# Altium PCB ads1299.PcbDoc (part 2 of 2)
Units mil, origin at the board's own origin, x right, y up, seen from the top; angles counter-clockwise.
Board outline 3937.01 x 3937.01 mil, 4 copper layers (Top Layer, internal_Layer 1, Internal_Layer 2, Bottom Layer), stack 23.756 mil thick; 175 components, 124 nets, 575 pads, 101 vias.
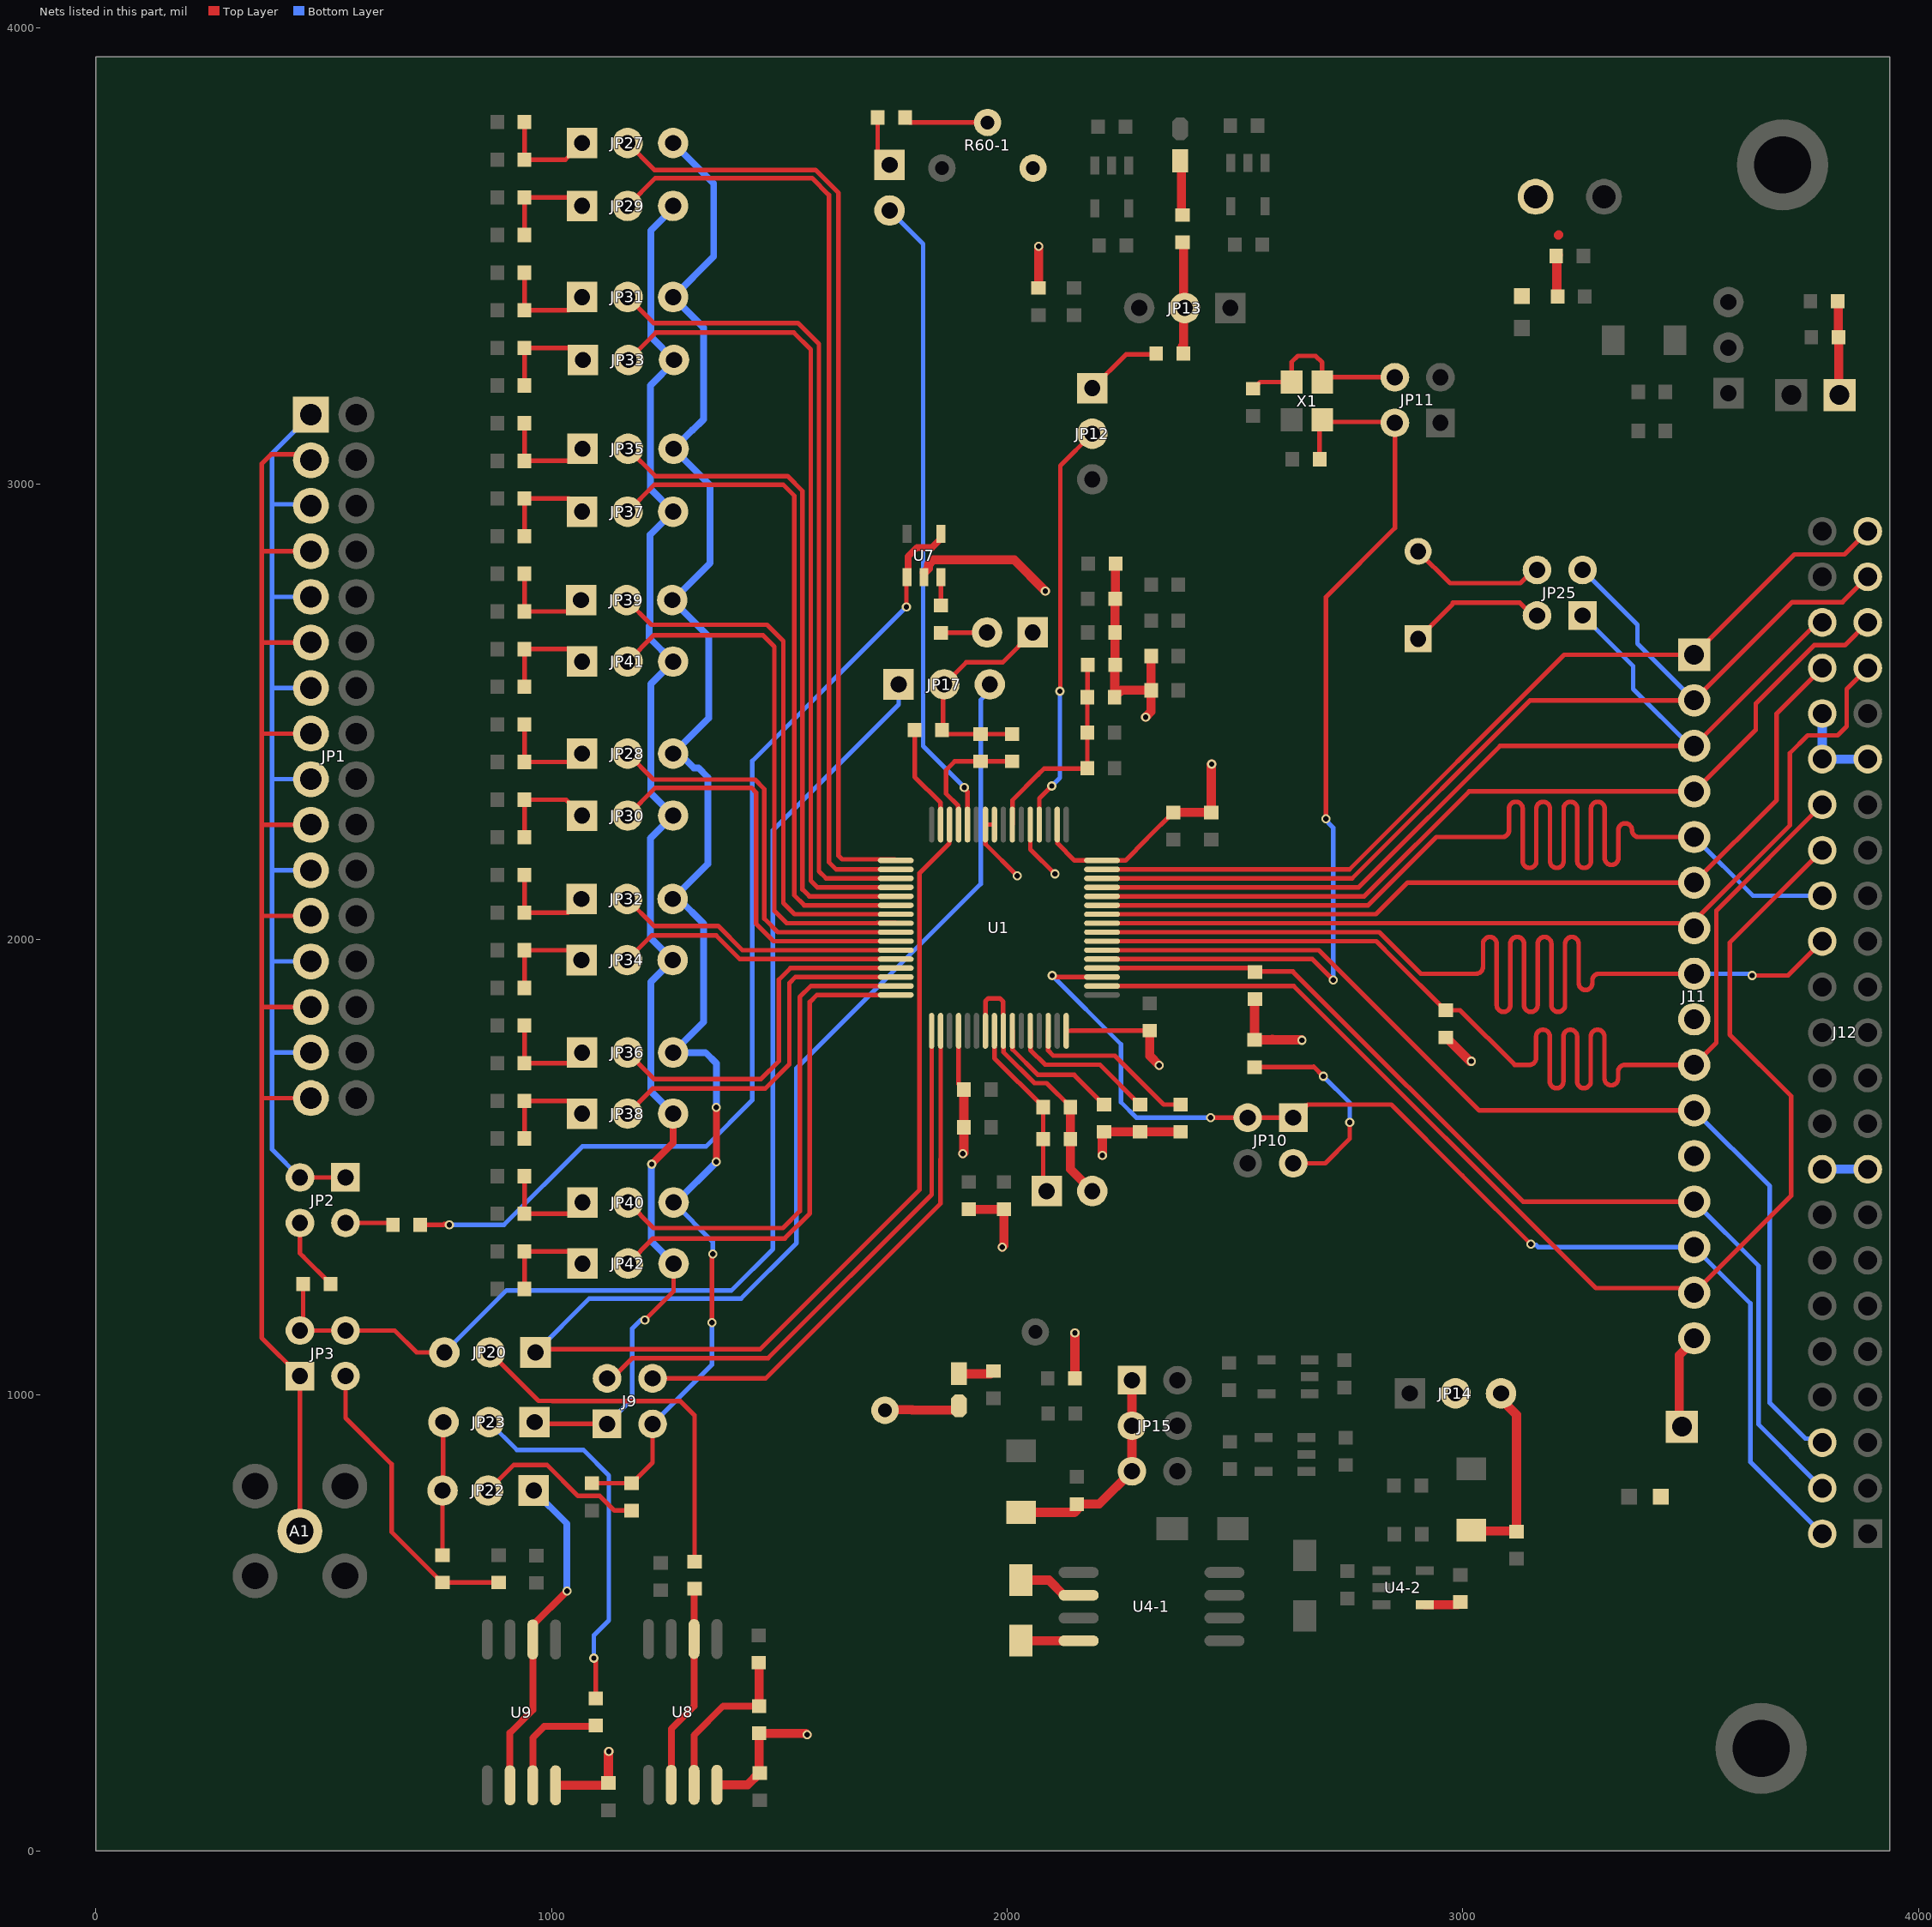
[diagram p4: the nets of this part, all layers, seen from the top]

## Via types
v1: diameter 20, hole 12, Top Layer to Bottom Layer, tented both sides, 86 vias
v2: diameter 20, hole 12, Top Layer to Bottom Layer, 15 vias

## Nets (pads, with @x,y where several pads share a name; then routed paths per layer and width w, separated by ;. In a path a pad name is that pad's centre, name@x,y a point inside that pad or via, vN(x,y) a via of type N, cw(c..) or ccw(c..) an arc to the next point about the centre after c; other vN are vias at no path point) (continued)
AVSS: C18.1 C19-1.1 C19-2.1 C21-1.1 C21-2.1 C23.1 C24.2 C25.1 C26.1 C28.1 C30.1 C32.2 C33.2 C53-1.1 C53-2.1 C55-3.2 C55-4.2 C56-1.1 C56-2.1 C62-2.1 C63-2.1 D2.K JP14.2 R60-1.3 R62-2.1 TP1.2 TP3.1 U1.20 U1.23 U1.25 U1.32 U1.53 U1.57 U1.58 U7.2 U8.4 U9.4 | length 3516.2
  Top Layer w10: U1.20@1893.42,1799.63 1893.42,1683.45 1905.08,1671.79 C19-1.1@1905.08,1671 ; U1.23@1952.47,1799.63 1952.47,1864.47 1959,1871 1984,1871 1991.49,1863.51 1991.49,1799.98 U1.25@1991.84,1799.63 1992.19,1799.28 1992.19,1753 2060.18,1685 2086.71,1685 2138.92,1632.79 C25.1@2138.92,1632 ; U1.57@1972.16,2252.37 U1.58@1952.47,2252.37 1952.56,2252.28 1952.56,2209.44 v1(2022,2140) ; U1.53@2050.9,2252.37 2050.9,2198.1 v1(2105,2144) ; U1.32@2129.64,1799.63 2140.32,1799.63 2140.84,1800.16 C33.2@2313,1800.16
  Top Layer w20: U9.4@1009,144 C62-2.1@1125.88,144 ; C62-2.1@1125,148.92 1125,217 v1(1126,218) ; U8.4@1363,145 1430.29,145 1456.21,170.92 C18.1@1457,170.92 ; 1455.5,187.42 1455.5,257.58 R62-2.1@1456,258.08 1557.92,258.08 v1(1561,255) ; TP3.1@1715,968 1791.65,968 1792,967.65 1886.76,967.65 1894.26,975.15 D2.K@1894.26,977 ; U7.2@1817.76,2805.2 1827.16,2814.6 1827.16,2822.65 1837.99,2833.48 2015.52,2833.48 v1(2084,2765) ; v1(1903,1530) 1905.08,1532.08 C19-2.1@1905.08,1588 C19-1.1@1905.08,1671 ; C21-1.1@1916,1408.08 C21-2.1@1993,1408.08 1993,1329 v1(1989,1325) ; C53-2.1@2069,3429.92 v1(2069,3521) ; C25.1@2138.92,1632 C24.2@2138.92,1562 2138.92,1496.08 TP1.2@2187,1448 ; C23.1@2148.92,1037 v1(2148.92,1136.92) ; v1(2209.15,1526.06) 2209.15,1574.23 C26.1@2213,1578.08 C28.1@2292,1578.08 C30.1@2381,1578.08 ; C55-4.2@2235.92,2532 2235.92,2532.79 C55-4.2@2236.42,2533.29 ; C56-1.1@2237.92,2825.79 C56-1.1@2237.92,2825 2237.42,2824.5 2237.42,2748.5 C56-2.1@2236.92,2748 C56-2.1@2236.92,2748 2236.88,2674.04 C53-1.1@2236.84,2674 2236.88,2673.96 C55-3.2@2236.92,2603 2236.42,2602.58 C55-4.2@2236.42,2533.29 ; v1(2304,2488) 2316.08,2500.08 C63-2.1@2316.08,2547 ; C33.2@2313,1800.16 2313,1745 v1(2334,1724) ; C32.2@2314.58,2623.5 C32.2@2316.08,2622 C63-2.1@2316.08,2547 ; C55-4.2@2236.42,2533.29 2240.88,2537.75 2241.67,2537.75 2250.92,2547 C63-2.1@2316.08,2547
BIAS: JP2.4 R62.1 | length 168.1
  Top Layer w10: JP2.4@443.46,1373.46 JP2.4@448,1378 448,1311.69 455.54,1304.15 514.92,1244.79 R62.1@514.92,1244
BIAS_DRV: C61.1 JP17.2 JP18.1 R61.2 R63-2.2 | length 501.2
  Top Layer w10: C61.1@2011,2450.92 R61.2@1942,2450.92 1866,2450.92 R63-2.2@1856.92,2460 1859.46,2462.54 1859.46,2557.46 JP17.2@1862,2560 1910.46,2608.46 1990.46,2608.46 JP18.1@2056,2674
BIAS_ELEC: JP3.2 JP3.4 JP17.1 JP20.3 R62.2 | length 2634.5
  Top Layer w10: R62.2@455.08,1244 455.08,1149.08 JP3.2@448,1142 JP3.4@548,1142 ; JP3.4@548,1156.34 JP3.4@548,1142 ; JP20.3@765,1094 704,1094 656,1142 JP3.4@548,1142
  Bottom Layer w10: JP20.3@765,1104 JP20.3@765,1094 901,1230 1395,1230 1486,1321 1486,2240.16 1762,2516.16 JP17.1@1762,2560
BIAS_SHD: R63.2 U7.1 U7.4 | length 2278.5
  Top Layer w10: R63.2@710.96,1373.04 R63.2@711.92,1374 763,1374 765,1376 765.09,1375.91 774.09,1375.91 v2(776,1374) ; v1(1779,2730) 1779,2794.32 U7.1@1780.2,2795.51
  Top Layer w15: U7.1@1780.2,2795.51 1782.54,2797.85 1782.54,2840.89 1802.14,2860.5 1835.34,2860.5 1852.66,2877.81 1852.66,2887.66 U7.4@1855,2890
  Bottom Layer w10: v2(776,1374) 895.85,1374 1067.85,1546 1339,1546 1441,1648 1441,2392 v1(1779,2730)
BIASIN: JP17.3 JP20.1 U1.62 | length 3893.5
  Top Layer w10: JP20.1@965,1094 972,1101 1458,1101 1808,1451 1808,2146.12 1872.96,2211.07 1872.96,2216.85 1873.38,2217.28 1873.38,2252.02 U1.62@1873.73,2252.37
  Bottom Layer w10: JP20.1@965,1094 1083,1212 1416,1212 1537.86,1333.86 1537.86,1717.86 1942,2122 1942,2525.68 1962,2545.68 JP17.3@1962,2560
BIASINV: C61.2 R61.1 U1.61 | length 283.9
  Top Layer w10: U1.61@1893.42,2252.37 1893.07,2252.72 1893.07,2287.46 1892.64,2287.9 1892.64,2293.67 1866,2320.3 1866,2372 1885.08,2391.08 R61.1@1942,2391.08 C61.2@2011,2391.08
BIASOUT: R63-2.1 U1.63 | length 231.2
  Top Layer w10: R63-2.1@1797.08,2460 1797.08,2356.92 1854.04,2299.96 U1.63@1854.05,2252.37
BIASREF: J16.2 U1.60 | length 1418.5
  Top Layer w10: v1(1906,2334) 1906,2331.29 1913.1,2324.19 U1.60@1913.1,2252.37
  Bottom Layer w10: J16.2@1742,3600 1815.54,3526.46 1815.54,2424.46 v1(1906,2334)
CLK: C37.2 JP11.2 U1.37 X1.3 | length 2044.3
  Top Layer w10: U1.37@2208.37,1957.1 2669.9,1957.1 v1(2716,1911) ; C37.2@2685.92,3054 2685.92,3135.12 X1.3@2691.46,3140.66 2696.13,3136 JP11.2@2826,3136 ; v1(2700,2265) 2700,2752.08 2851,2903.08 JP11.2@2851,3134
  Bottom Layer w10: v1(2700,2265) 2700,2262.29 2705,2257.29 2705,2256 2716,2245 v1(2716,1911)
CLKSEL: JP12.2 U1.52 | length 919.3
  Top Layer w10: U1.52@2070.58,2252.37 2070.58,2309.58 v1(2098,2337) ; v1(2116,2545) 2117,2546 2117,3040 JP12.2@2187,3110 ; JP12.2@2195,3090 JP12.2@2204.5,3099.5
  Bottom Layer w10: v1(2098,2337) 2116,2355 v1(2116,2545)
CS#: J11.10 J12.33 R39.2 U1.39 | length 2775
  Top Layer w10: U1.39@2208.37,1996.47 2809.99,1996.47 2848.1,1958.36 R39.2@2961.87,1844.58 ; R39.2@2963,1844.92 2994.08,1844.92 3114,1725 3141,1725 3146,1725 ccw(c3146,1740) 3161,1740 3161,1787.2 cw(c3176,1787.2) 3191,1787.2 3191,1688.8 ccw(c3206,1688.8) 3221,1688.8 3221,1787.2 cw(c3236,1787.2) 3251,1787.2 3251,1688.8 ccw(c3266,1688.8) 3281,1688.8 3281,1787.2 cw(c3296,1787.2) 3311,1787.2 3311,1695.08 ccw(c3326,1695.08) 3341,1695.08 3341,1710 cw(c3356,1710) 3356,1725 3413,1725 J11.10@3508,1725 ; J11.10@3519,1725 3519,1736 3556.43,1773.43 3556.43,2063.43 J12.33@3789,2296
  Bottom Layer w10: J12.33@3779.58,2286.58 J12.33@3789,2296
DAISY_IN: J11.7 J12.40 U1.41 | length 2071.6
  Top Layer w10: U1.41@2208.37,2035.84 3497.16,2035.84 J11.7@3508,2025 3508,2040.46 3718,2250.46 3718,2409 3757,2448 3823,2448 3842.81,2467.81 3842.81,2549.81 J12.40@3889,2596
DGND: C0-5.1 C0-6.1 J11.16 J12.17 J12.18 J12.35 J12.36 J12.37 J13-1.1 J13-2.1 L3.2 | length 730.9
  Top Layer w20: J13-2.1@3481,931 3475,937 3475,1087.85 3508,1120.85 J11.16@3508,1125 ; C0-5.1@3823,3401 3823.96,3400.04 3823.96,3322.96 C0-6.1@3824.92,3322 3824.92,3197.08 J13-1.1@3827,3195
  Bottom Layer w20: J13-2.1@3480,932 J13-2.1@3481,931 ; J12.17@3789,1484.37 J12.17@3789,1496 J12.18@3889,1496 ; J12.37@3789,2496 J12.35@3789,2396 J12.36@3889,2396
DIN: J11.15 J12.31 U1.34 | length 2777.6
  Top Layer w10: U1.34@2208.37,1898.05 2327.07,1898.05 ; 2327.08,1898.04 2628.96,1898.04 3292,1235 3498,1235 J11.15@3508,1225 3721,1438 3721,1656.21 3586,1791.21 3586,1993 J12.31@3789,2196
DOUT: J11.5 J12.29 U1.43 | length 2776
  Top Layer w10: U1.43@2208.37,2075.21 2792.21,2075.21 2942,2225 3081.5,2225 3086.5,2225 ccw(c3086.5,2240) 3101.5,2240 3101.5,2287.37 cw(c3116.5,2287.37) 3131.5,2287.37 3131.5,2172.07 ccw(c3146.5,2172.07) 3161.5,2172.07 3161.5,2287.37 cw(c3176.5,2287.37) 3191.5,2287.37 3191.5,2172.07 ccw(c3206.5,2172.07) 3221.5,2172.07 3221.5,2287.37 cw(c3236.5,2287.37) 3251.5,2287.37 3251.5,2172.07 ccw(c3266.5,2172.07) 3281.5,2172.07 3281.5,2287.37 cw(c3296.5,2287.37) 3311.5,2287.37 3311.5,2178.94 ccw(c3326.5,2178.94) 3341.5,2178.94 3341.5,2240 cw(c3356.5,2240) 3371.5,2240 ccw(c3386.5,2240) 3386.5,2225 3436,2225 J11.5@3508,2225
  Bottom Layer w10: J11.5@3508,2225 3637,2096 J12.29@3789,2096
DRDY#: J11.1 J12.46 U1.47 | length 1988
  Top Layer w10: U1.47@2208.37,2153.95 2751.49,2153.95 3222.54,2625 J11.1@3508,2625 3728,2845 3838,2845 J12.46@3889,2896
DVDD: C48-1.2 C49-1.2 J11.9 J11.12 JP13.2 R35.1 R36.2 R39.1 R48.2 R52.2 U1.48 U1.50 | length 1047.4
  Top Layer w10: U1.50@2109.95,2252.37 2110.3,2252.02 2110.3,2211.51 2148.17,2173.64 U1.48@2208.37,2173.64 2259.72,2173.64 2306.99,2220.91 2306.99,2221.69 2364.21,2278.92 C48-1.2@2365,2278.92
  Top Layer w20: C48-1.2@2365,2278.92 C49-1.2@2448,2278.92 2448,2384 v1(2449,2385) ; 2384.92,3302 2387.46,3304.54 2387.46,3383.46 JP13.2@2390,3386 2387.5,3388.5 2387.5,3527.66 R48.2@2385,3530.16 ; R36.2@2543,1868.08 R35.1@2543,1779.92 v1@2646.08,1779.92 ; 2582.08,1780.92 2583,1780 ; R39.1@2963,1785.08 2963.79,1785.08 3015.87,1733 v1(3019,1733)
  other v1: 2647,1779
GND_EXT: C0-3.1 C0-4.1 L2.1 Power.2 | length 95.9
  Top Layer w20: L2.1@3130,3412 L2.1@3130.5,3411.5 ; C0-4.1@3208.08,3411 3206.58,3412.5 3206.58,3499.29 C0-3.1@3210.04,3502.75 ; 3210.04,3545.75 3211,3546.71
GPIO1: J11.6 J12.39 U1.42 | length 1915.4
  Top Layer w10: U1.42@2208.77,2055.53 2809.53,2055.53 2879,2125 J11.6@3508,2125 3689,2306 3689,2496 J12.39@3789,2596
GPIO2: J11.4 J12.42 U1.44 | length 1963.6
  Top Layer w10: U1.44@2208.37,2094.9 2783.9,2094.9 3014,2325 J11.4@3508,2325 3643,2460 3643,2518 3771,2646 3839,2646 J12.42@3889,2696
GPIO3: J11.3 J12.41 JP25.1 U1.45 | length 2214.2
  Top Layer w10: U1.45@2208.37,2114.58 2771.58,2114.58 3082,2425 J11.3@3508,2425 3779,2696 J12.41@3789,2696
  Bottom Layer w10: JP25.1@3263,2711 3374,2600 3374,2550 3499,2425 J11.3@3508,2425
GPIO4: J11.2 J12.44 JP25.3 U1.46 | length 2342.2
  Top Layer w10: U1.46@2208.37,2134.27 2757.26,2134.27 3147.99,2525 J11.2@3508,2525 3723.5,2740.5 3833.5,2740.5 J12.44@3889,2796
  Bottom Layer w10: JP25.3@3263,2811 3383.32,2690.68 3383.32,2649.68 J11.2@3508,2525
IN1_N: JP40.2 U1.15 | length 1106.1
  Top Layer w10: JP40.2@1168,1423 1224,1367 1508,1367 1545,1404 1545,1874 1569.05,1898.05 U1.15@1755.63,1898.05
IN1_P: JP42.2 U1.16 | length 1103.6
  Top Layer w10: JP42.2@1168,1289 1223,1344 1512,1344 1567,1399 1567,1863 1582.36,1878.36 U1.16@1755.63,1878.36
IN2_N: JP36.2 U1.13 | length 818.3
  Top Layer w10: JP36.2@1167,1752 1225,1694 1460,1694 1499,1733 1499,1912 1524.42,1937.42 U1.13@1755.63,1937.42
IN2_P: JP38.2 U1.14 | length 817.3
  Top Layer w10: JP38.2@1167,1618 1222,1673 1469,1673 1522,1726 1522,1904.42 1535.31,1917.73 U1.14@1755.63,1917.73
IN3_N: JP32.2 U1.11 | length 636.1
  Top Layer w10: JP32.2@1166,2089 1225,2030 1365.92,2030 1419.13,1976.79 U1.11@1755.63,1976.79
IN3_P: JP34.2 U1.12 | length 633.5
  Top Layer w10: JP34.2@1166,1955 1220,2009 1361.47,2009 1413.37,1957.1 U1.12@1755.63,1957.1
IN4_N: JP28.2 U1.9 | length 917.6
  Top Layer w10: JP28.2@1167,2408 1224,2351 1446.46,2351 1467,2330.46 1467,2046 1496.84,2016.16 U1.9@1755.63,2016.16
IN4_P: JP30.2 U1.10 | length 922
  Top Layer w10: JP30.2@1167,2272 1228,2333 1439,2333 1449,2323 1449,2035 1487.53,1996.47 U1.10@1755.63,1996.47
IN5_N: JP39.2 U1.7 | length 1213
  Top Layer w10: JP39.2@1165,2745 1219,2691 1473,2691 1509,2655 1509,2080 1533.47,2055.53 U1.7@1755.63,2055.53
IN5_P: JP41.2 U1.8 | length 1254.9
  Top Layer w10: JP41.2@1167,2610 1225,2668 1464,2668 1489,2643 1489,2063 1516.16,2035.84 1715.62,2035.84 U1.8@1755.63,2035.84 1755.28,2036.19 1715.62,2036.19 1715.26,2036.55
IN6_N: JP35.2 U1.5 | length 1506.4
  Top Layer w10: JP35.2@1168,3077 1228,3017 1518,3017 1551,2984 1551,2110 1566,2095 1755.53,2095 U1.5@1755.63,2094.9
IN6_P: JP37.2 U1.6 | length 1509
  Top Layer w10: JP37.2@1167,2939 1226,2998 1509,2998 1533,2974 1533,2097 1554.79,2075.21 U1.6@1755.63,2075.21
IN7_N: JP31.2 U1.3 | length 1794.8
  Top Layer w10: JP31.2@1167,3410 1224,3353 1541,3353 1587,3307 1587,2150 1602.73,2134.27 U1.3@1755.63,2134.27
IN7_P: JP33.2 U1.4 | length 1798.8
  Top Layer w10: JP33.2@1169,3272 1229,3332 1532,3332 1569,3295 1569,2129 1583.42,2114.58 U1.4@1755.63,2114.58
IN8_N: JP27.2 U1.1 | length 2092.8
  Top Layer w10: JP27.2@1167,3748 1226,3689 1579.46,3689 1630,3638.46 1630,2184 1638,2176 1753.27,2176 U1.1@1755.63,2173.64
IN8_P: JP29.2 U1.2 | length 2099.9
  Top Layer w10: JP29.2@1167,3610 1228,3671 1572,3671 1609,3634 1609,2170 1625.05,2153.95 U1.2@1755.63,2153.95
IN+: A1.1 JP1.3 JP1.7 JP1.11 JP1.15 JP1.19 JP1.23 JP1.27 JP1.31 JP3.1 | length 3255
  Top Layer w10: A1.1@448,702 JP3.1@448,1042 364,1126 364,1652 ; JP1.31@472,1652 364,1652 ; JP1.27@472,1852 364,1852 ; JP1.23@472,2052 364,2052 ; JP1.19@472,2252 364,2252 ; JP1.15@472,2452 364,2452 ; JP1.11@472,2652 364,2652 ; JP1.7@472,2852 364,2852 ; JP1.3@472,3052 458.85,3065.15 385.15,3065.15 364,3044 364,2852 ; 364,1652 364,1852 ; 364,1852 364,2052 ; 364,2052 364,2252 ; 364,2252 364,2452 ; 364,2452 364,2652 ; 364,2652 364,2852
IN-: JP1.1 JP1.5 JP1.9 JP1.13 JP1.17 JP1.21 JP1.25 JP1.29 JP2.1 JP2.3 | length 2430.9
  Top Layer w10: JP2.3@448,1478 JP2.1@548,1478
  Bottom Layer w10: JP2.3@448,1478 387,1539 387,1752 ; JP1.29@472,1752 387,1752 ; JP1.25@472,1952 387,1952 ; JP1.21@472,2152 387,2152 ; JP1.17@472,2352 387,2352 ; JP1.13@472,2552 387,2552 ; JP1.9@472,2752 387,2752 ; JP1.5@472,2952 468.63,2955.37 387,2955.37 ; JP1.1@472,3152 387,3067 387,2955.37 ; 387,1752 387,1952 ; 387,1952 387,2152 ; 387,2152 387,2352 ; 387,2352 387,2552 ; 387,2552 387,2752 ; 387,2752 387,2955.37
NetC0-8_2: C0-8.2 JP15.1 JP15.3 JP15.5 L4.2 | length 484.6
  Top Layer w20: L4.2@2031,743 2147.79,743 C0-8.2@2159.79,755 ; C0-8.2@2153,761 2202,761 JP15.5@2274,833 JP15.3@2274,933 JP15.1@2274,1033
NetC0-10_2: C0-10.2 JP14.3 L5.2 | length 417.2
  Top Layer w20: L5.2@3019,703.5 3020.29,702.21 3116.71,702.21 C0-10.2@3118,700.92 3118,957.3 3084,991.3 JP14.3@3084,1004
NetC1-1_2: C1-1.2 JP27.1 R1-1.2 | length 223.9
  Top Layer w10: R1-1.2@940.92,3794 C1-1.2@940.92,3711.39 1030.39,3711.39 JP27.1@1067,3748
NetC2-1_1: C2-1.1 JP29.1 R2-1.2 | length 216.5
  Top Layer w10: R2-1.2@940.92,3546.16 C2-1.1@940.92,3628.77 1048.23,3628.77 JP29.1@1067,3610
NetC3-1_2: C3-1.2 JP31.1 R3-1.2 | length 220.7
  Top Layer w10: R3-1.2@940.92,3463.55 C3-1.2@940.92,3380.94 1037.94,3380.94 JP31.1@1067,3410
NetC4-1_1: C4-1.1 JP33.1 R4-1.2 | length 221.6
  Top Layer w10: R4-1.2@940.92,3215.71 C4-1.1@940.92,3298.32 1042.68,3298.32 JP33.1@1069,3272
NetC5-1_2: C5-1.2 JP35.1 R5-1.2 | length 220.7
  Top Layer w10: R5-1.2@940.92,3133.1 C5-1.2@940.92,3050.48 1041.48,3050.48 JP35.1@1068,3077
NetC6-1_1: C6-1.1 JP37.1 R6-1.2 | length 220.7
  Top Layer w10: R6-1.2@940.92,2885.26 C6-1.1@940.92,2967.87 1038.13,2967.87 JP37.1@1067,2939
NetC7-1_2: C7-1.2 JP39.1 R7-1.2 | length 217
  Top Layer w10: R7-1.2@940.92,2802.65 C7-1.2@940.92,2720.03 1040.03,2720.03 JP39.1@1065,2745
NetC8-1_1: C8-1.1 JP41.1 R8-1.2 | length 220
  Top Layer w10: R8-1.2@940.92,2554.81 C8-1.1@940.92,2637.42 1039.58,2637.42 JP41.1@1067,2610
NetC9-1_2: C9-1.2 JP28.1 R9-1.2 | length 216.3
  Top Layer w10: R9-1.2@940.92,2472.19 C9-1.2@940.92,2389.58 1048.58,2389.58 JP28.1@1067,2408
NetC10-1_1: C10-1.1 JP30.1 R10-1.2 | length 223.2
  Top Layer w10: R10-1.2@940.92,2224.35 C10-1.1@940.92,2306.97 1032.03,2306.97 JP30.1@1067,2272
NetC11-1_2: C11-1.2 JP32.1 R11-1.2 | length 220.1
  Top Layer w10: R11-1.2@940.92,2141.74 C11-1.2@940.92,2059.13 1036.13,2059.13 JP32.1@1066,2089
NetC12-1_1: C12-1.1 JP34.1 R12-1.2 | length 216.6
  Top Layer w10: R12-1.2@940.92,1893.9 C12-1.1@940.92,1976.52 1044.48,1976.52 JP34.1@1066,1955
NetC13-1_2: C13-1.2 JP36.1 R13-1.2 | length 218.4
  Top Layer w10: R13-1.2@940.92,1811.29 C13-1.2@940.92,1728.68 1043.68,1728.68 JP36.1@1067,1752
NetC14-1_1: C14-1.1 JP38.1 R14-1.2 | length 220.3
  Top Layer w10: R14-1.2@940.92,1563.45 C14-1.1@940.92,1646.06 1038.94,1646.06 JP38.1@1067,1618
NetC15-1_2: C15-1.2 JP40.1 R15-1.2 | length 220
  Top Layer w10: R15-1.2@940.92,1480.84 C15-1.2@940.92,1398.23 1043.23,1398.23 JP40.1@1068,1423
NetC16-1_1: C16-1.1 JP42.1 R16-1.2 | length 220.7
  Top Layer w10: R16-1.2@940.92,1233 C16-1.1@940.92,1315.61 1041.39,1315.61 JP42.1@1068,1289
NetC17_2: C17.2 JP3.3 R17.2 | length 664.6
  Top Layer w10: JP3.3@548,1042 548,950 649.13,848.87 649.13,700.17 760.21,589.08 R17.2@761,589.08 C17.2@884,589.08
NetC38_1: C38.1 JP11.4 X1.1 X1.4 | length 420.4
  Top Layer w10: C38.1@2540,3208.84 2540.79,3208.84 2555.28,3223.34 X1.1@2624.54,3223.34 2624.54,3267.54 2638,3281 2677,3281 2691.46,3266.54 X1.4@2691.46,3223.34 2702.13,3234 JP11.4@2851,3234
NetC57-1_1: C57-1.1 U4-1.2 | length 140.8
  Top Layer w20: C57-1.1@2030,594.39 2091.61,594.39 2125,561 U4-1.2@2157,561
NetC57-1_2: C57-1.2 U4-1.4 | length 127.3
  Top Layer w20: C57-1.2@2030,461.61 2030.61,461 U4-1.4@2157,461
NetC58-2_2: C58-2.2 U4-2.4 | length 80.9
  Top Layer w20: U4-2.4@2916.49,540.2 2988.33,540.2 2994.21,546.08 C58-2.2@2995,546.08
NetD1_A: D1.A R48.1 | length 121.2
  Top Layer w20: D1.A@2379.74,3709 2382.37,3706.38 2382.37,3592.63 R48.1@2385,3590
NetD2_A: D2.A R21.1 | length 78.2
  Top Layer w20: D2.A@1894.26,1047 1963.29,1047 1969.21,1052.92 R21.1@1970,1052.92
NetJ16_1: J16.1 R60-2.2 | length 114.7
  Top Layer w10: R60-2.2@1716.08,3804 1716.08,3725.92 J16.1@1742,3700
NetJP10_2: JP10.2 R35.2 | length 481.9
  Top Layer w10: R35.2@2543,1720.08 2671.92,1720.08 2672.92,1721.08 v1(2694,1700) ; JP10.2@2638.14,1498.86 JP10.2@2628,1509 2698,1509 2752,1563 v1(2752,1599)
  Bottom Layer w10: v1(2694,1700) 2752,1642 v1(2752,1599)
NetJP12_1: JP12.1 R52.1 | length 159.6
  Top Layer w10: JP12.1@2187,3210 2261,3284 R52.1@2315.99,3284
NetJP18_2: JP18.2 R63-1.2 | length 101.4
  Top Layer w10: R63-1.2@1855,2673.08 1855.46,2673.54 1955.54,2673.54 JP18.2@1956,2674
NetJP20_2: JP20.2 R62-3.2 | length 827.2
  Top Layer w10: JP20.2@865,1094 971.54,987.46 1001.85,987.46 1002.31,987 1283,987 1314,956 R62-3.2@1314,635
NetJP22_1: JP22.1 U9.2 U9.6 | length 728
  Top Layer w15: U9.2@909,144 909,259 959,309 959,495.5 1033.5,570 v1(1034,570)
  Bottom Layer w15: JP22.1@961,791 1034,718 v1@1034,571.35
NetJP22_2: JP22.2 R17-1.1 | length 389.5
  Top Layer w10: JP22.2@861,791 917,847 990.31,847 1058.31,779 1067.83,779 1067.87,778.96 1106.21,778.96 1138.09,747.08 R17-1.1@1176,747.08 R17-1.1@1183,740.08
NetJP23_2: JP23.2 R23.1 | length 815.9
  Top Layer w10: v1(1093,423) 1093,420.29 1097,416.29 R23.1@1097,334.92
  Bottom Layer w10: JP23.2@863,941 924.2,879.8 1070.2,879.8 1126,824 1126,506.15 1093,473.15 v1(1093,423)
NetR23_2: R23.2 U9.3 | length 252.4
  Top Layer w15: U9.3@959,144 959,248 984.08,273.08 R23.2@1097,273.08
NetR60-1_2: R60-1.2 R60-2.1 | length 186.1
  Top Layer w10: R60-2.1@1775.92,3804 1775.92,3803.21 1786.13,3793 R60-1.2@1957,3793
NetR62-1_1: R62-1.1 R62-2.2 U8.3 | length 374
  Top Layer w15: U8.3@1313,145 1313,254 1376.92,317.92 R62-2.2@1456,317.92
  Top Layer w20: R62-1.1@1455,413.08 1455.5,412.58 1455.5,318.42 R62-2.2@1456,317.92
NetR62-3_1: R62-3.1 U8.2 U8.6 | length 451.3
  Top Layer w15: U8.2@1263,145 1263,268 1313,318 U8.6@1313,465 1313.5,465.5 1313.5,574.66 R62-3.1@1314,575.16
NetR63-1_1: R63-1.1 U7.3 | length 62.6
  Top Layer w10: R63-1.1@1855,2732.92 U7.3@1855,2795.51
PACEOUT1/SRB1: J9.2 U1.17 | length 1238.7
  Top Layer w10: J9.2@1131.18,1046.18 1142.18,1046.18 1177.5,1081.5 1475.5,1081.5 1834.36,1440.36 U1.17@1834.36,1799.63
  Top Layer w15: J9.2@1122,1037 J9.2@1131.18,1046.18
PACEOUT2/SRB2: J9.4 U1.18 | length 1170
  Top Layer w10: J9.4@1222,1037 1470,1037 1854,1421 1854,1518.05 1854.36,1518.41 1854.36,1799.32 U1.18@1854.05,1799.63
PWDN#: J11.14 J12.1 JP10.1 JP10.3 U1.35 | length 2610.4
  Top Layer w10: v1(2099,1921) 2101.71,1921 2104.98,1917.73 U1.35@2208.37,1917.73 ; v1(2447,1609) JP10.3@2528,1609 JP10.1@2628,1609 2654.5,1635.5 2657.85,1635.5 2660.35,1638 2843.02,1638 2998.86,1482.15 v1(3149.55,1331.46)
  Bottom Layer w10: v1(2099,1921) 2250,1770 2250,1643 2284,1609 v1(2447,1609) ; v1(3149.55,1331.46) 3151.47,1329.55 3161.24,1329.55 3165.79,1325 J11.14@3508,1325 3631.25,1201.75 3631.25,853.75 J12.1@3789,696
REF_ELEC: JP22.3 JP23.3 R17.1 | length 292.9
  Top Layer w10: R17.1@761,648.92 JP22.3@761,791 762,792 762,940 JP23.3@763,941
RESET#: J11.13 J12.3 R36.1 U1.36 | length 2257.7
  Top Layer w10: U1.36@2208.37,1937.42 2535.5,1937.42 R36.1@2544,1928.92 ; R36.1@2544,1929.92 2627.08,1929.92 3132,1425 J11.13@3508,1425
  Bottom Layer w10: J11.13@3508,1425 3649.25,1283.75 3649.25,935.75 J12.3@3789,796
SCLK: J11.8 J12.27 U1.40 | length 2753.6
  Top Layer w10: U1.40@2208.37,2016.16 2816.84,2016.16 2908,1925 3024.5,1925 3029.5,1925 ccw(c3029.5,1940) 3044.5,1940 3044.5,1990.68 cw(c3059.5,1990.68) 3074.5,1990.68 3074.5,1856.34 ccw(c3089.5,1856.34) 3104.5,1856.34 3104.5,1990.68 cw(c3119.5,1990.68) 3134.5,1990.68 3134.5,1856.34 ccw(c3149.5,1856.34) 3164.5,1856.34 3164.5,1990.68 cw(c3179.5,1990.68) 3194.5,1990.68 3194.5,1856.34 ccw(c3209.5,1856.34) 3224.5,1856.34 3224.5,1990.68 cw(c3239.5,1990.68) 3254.5,1990.68 3254.5,1904.33 ccw(c3269.5,1904.33) 3284.5,1904.33 3284.5,1910 cw(c3299.5,1910) 3299.5,1925 3405,1925 J11.8@3507.68,1925 ; v1(3635,1921) 3714,1921 J12.27@3789,1996
  Bottom Layer w10: J11.8@3508,1925 3628.29,1925 3632.29,1921 v1(3635,1921)
SHD: JP2.2 R63.1 | length 109.9
  Top Layer w10: JP2.2@549.46,1376.54 JP2.2@548,1378 648.08,1378 R63.1@652.08,1374 ; R63.1@646.54,1371.54 R63.1@648,1370.08
SRB1: C17-2.2 J9.3 JP27.3 JP28.3 JP31.3 JP32.3 JP35.3 JP36.3 JP39.3 JP40.3 R17-1.2 | length 3666
  Top Layer w10: C17-2.2@1089,806.92 1175.92,806.92 1175.96,806.96 1176.83,806.96 1222,852.13 J9.3@1222,937 ; v2(1352,1159) 1352,1308 v2(1354,1310)
  Top Layer w15: v2(1362,1512) v2(1362,1632)
  Bottom Layer w10: J9.3@1222,937 1352,1067 v2(1352,1159) ; JP40.3@1268,1423 1354,1337 v2(1354,1310)
  Bottom Layer w15: JP27.3@1267,3748 1356,3659 1356,3499 JP31.3@1267,3410 1334,3343 1334,3141.79 1310.09,3117.87 1308.87,3117.87 JP35.3@1268,3077 1348,2997 1348,2826 1267,2745 JP39.3@1265,2745 1345,2665 1345,2486 JP28.3@1267,2408 1281.05,2408 1312.2,2376.85 1322.36,2376.85 1343,2356.21 1343,2166 JP32.3@1266,2089 1280,2089 1334,2035 1334,1819 JP36.3@1267,1752 1338,1752 1362,1728 v2(1362,1632) ; JP40.3@1268,1423 1273,1423 v2(1362,1512)
SRB2: J9.1 JP23.1 JP29.3 JP30.3 JP33.3 JP34.3 JP37.3 JP38.3 JP41.3 JP42.3 | length 3189.1
  Top Layer w10: JP23.1@967,937 J9.1@1122,937 ; v2(1205,1165) 1268,1228 JP42.3@1268,1289
  Top Layer w15: JP23.1@963,941 JP23.1@967,937 ; v2(1220,1507) 1267,1554 JP38.3@1267,1618
  Bottom Layer w10: J9.1@1122,937 1177.5,992.5 1177.5,1146.5 1196.36,1165.36 1204.64,1165.36 v2(1205,1165)
  Bottom Layer w15: v2(1220,1507) 1220,1500 1219.04,1499.04 1219.04,1337.96 JP42.3@1268,1289 ; JP38.3@1267,1618 1218.04,1666.96 1218.04,1907.04 JP34.3@1266,1955 1217,2004 1217,2222 JP30.3@1267,2272 1218,2321 1218,2561 JP41.3@1267,2610 1214,2663 1214,2688 1216.04,2690.04 1216.04,2888.04 JP37.3@1267,2939 1217,2989 1217,3216 1269,3268 JP33.3@1269,3272 1218.04,3322.96 1218.04,3556.04 1267,3605 JP29.3@1267,3610
START: J11.11 J12.5 U1.38 | length 2310.8
  Top Layer w10: U1.38@2208.37,1976.79 2684.27,1976.79 3036.06,1625 J11.11@3508,1625 J11.11@3505.42,1627.58
  Bottom Layer w10: J11.11@3508,1625 3674,1459 3674,983 3752.12,904.88 3780.12,904.88 J12.5@3789,896
VCAP1: C28.2 U1.28 | length 332.5
  Top Layer w10: U1.28@2050.9,1799.63 2051.25,1799.28 2051.25,1757.67 2083.65,1725.26 2203.87,1725.26 2291.21,1637.92 C28.2@2292,1637.92
VCAP2: C30.2 U1.30 | length 383.1
  Top Layer w10: U1.30@2090.27,1799.63 2090.27,1756.29 2101.29,1745.26 2236.58,1745.26 2343.92,1637.92 C30.2@2381,1637.92
VCAP3: C55-1.2 C55-2.2 C55-3.1 C55-4.1 U1.55 | length 474.8
  Top Layer w10: U1.55@2011.53,2252.37 2011.88,2252.72 2011.88,2305.87 2068.24,2362.23 2081.22,2375.21 2176.08,2375.21 C55-2.2@2176.08,2376 C55-1.2@2176.08,2454 C55-4.1@2176.08,2532 ; C55-4.1@2176.58,2532.5 C55-3.1@2176.58,2602.5
  Top Layer w20: C55-4.1@2176.08,2532 C55-4.1@2176.58,2532.5 ; C55-3.1@2176.58,2602.5 C55-3.1@2177.08,2603
VCAP4: C26.2 U1.26 | length 292.2
  Top Layer w10: U1.26@2011.53,1799.63 2011.88,1799.28 2011.88,1758.76 2067.64,1703 2147.13,1703 2212.21,1637.92 C26.2@2213,1637.92
VREFP: C24.1 C25.2 TP1.1 U1.24 | length 399.2
  Top Layer w10: U1.24@1972.16,1799.63 1972.16,1739.71 2079.08,1632.79 C25.2@2079.08,1632 C24.1@2079.08,1562 2079.08,1455.92 TP1.1@2087,1448
X2-1: JP25.2 X2.1 | length 307.3
  Top Layer w10: X2.1@2902,2659.94 2978,2735.94 2978,2739.14 3125.39,2739.14 3153.53,2711 JP25.2@3163,2711
X2-2: JP25.4 X2.2 | length 302
  Top Layer w10: X2.2@2902,2852.06 2972.06,2782 3126.24,2782 3155.24,2811 JP25.4@3163,2811
pads on no net: J12.2 J12.4 J12.6 J12.7 J12.8 J12.9 J12.10 J12.11 J12.12 J12.13 J12.14 J12.15 J12.16 J12.19 J12.20 J12.21 J12.22 J12.23 J12.24 J12.25 J12.26 J12.28 J12.30 J12.32 J12.34 J12.38 J12.43 U1.27 U1.29 U4-1.1 U4-1.7 U8.1 U8.5 U8.8 U9.1 U9.5 U9.8

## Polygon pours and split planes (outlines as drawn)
+5V_EXT on Top Layer "+5V_EXT_L01_P012" (solid, remove dead copper, pour order 12): 3357.03,3379 3643,3379 3643,3474 3359,3474 3358,3475
+5V_EXT on Top Layer "+5V_EXT_L01_P010" (solid, remove dead copper, pour order 10): 3250,3682 3247,3679 3247,3378 3379,3378 3379,3681.06
AGND on Top Layer "AGND_L01_P000" (solid, remove dead copper, pour order 0): 1724.64,1247.37 3310.13,1247.37 3391.51,1165.99 3391.51,396.99 3296.76,302.24 1709.68,302.24 1665.51,386.61 1665.51,1188.24
DGND on Top Layer "DGND_L01_P008" (solid, remove dead copper, pour order 8): 3601,1139 3613,1139 3625,1139 3704,1139 3704,615 3422,615 3422,1139
DGND on Top Layer "DGND_L01_P007" (solid, pour order 7): 3658,3457.58 3937.01,3457.58 3937.01,615 3658,615
AGND on Top Layer "AGND_L01_P006" (solid, remove dead copper, pour order 6): 3029,3362 3243,3362 3243,3215 3029,3215
GND_EXT on Top Layer "GND_EXT_L01_P005" (solid, pour order 5): 3241,3684 3237,3680 3237,3376 3093,3376 3093,3403 3093,3684
+5V on Top Layer "+5V_L01_P004" (solid, remove dead copper, pour order 4): 3254,3367 3409,3367 3409,3056 3252,3056 3252,3368
AGND on internal_Layer 1 (split plane): 3916.91,20.1 20.1,20.1 20.1,3916.91 3916.91,3916.91
AVSS on Internal_Layer 2 (split plane): 197 vertices, not listed, extent 20.1,20.1 3418.44,3916.91
AVDD on Internal_Layer 2 (split plane): 1942.44,3264 1942.69,3262.04 1943.45,3260.22 1944.65,3258.65 1946.22,3257.45 1948.04,3256.69 1950,3256.44 2231.21,3256.44 2232.21,3255.13 2233.78,3253.93 2235.6,3253.17 2237.56,3252.92 2239.52,3253.17 2241.34,3253.93 2242.91,3255.13 2243.91,3256.44 2418.44,3256.44 2418.44,2907 2418.69,2905.04 2419.45,2903.22 2420.65,2901.65 2422.22,2900.45 2422.44,2900.36 2422.44,2814.56 2007,2814.56 2005.04,2814.31 2003.22,2813.55 2001.65,2812.35 2000.45,2810.78 1999.69,2808.96 1999.44,2807 1999.44,2641.56 1999.44,2396.12 1999.69,2394.16 2000.14,2393.09 2000.45,2392.34 2001.65,2390.77 2030.99,2361.43 2030.99,2213.56 1972,2213.56 1970.04,2213.31 1968.22,2212.55 1966.65,2211.35 1965.45,2209.78 1964.69,2207.96 1964.44,2206 1964.44,1973 1964.69,1971.04 1965.45,1969.22 1966.65,1967.65 1968.22,1966.45 1970.04,1965.69 1972,1965.44 2021.44,1965.44 2021.44,1643.56 1560,1643.56 1558.04,1643.31 1556.22,1642.55 1554.65,1641.35 1553.45,1639.78 1552.69,1637.96 1552.44,1636 1552.44,1044 1552.44,915 1552.69,913.04 1553.14,911.97 1553.45,911.22 1554.65,909.65 1570.65,893.65 1572.22,892.45 1574.04,891.69 1574.27,891.66 1576,891.44 1833.44,891.44 1833.44,806 1833.69,804.04 1834.44,802.25 1834.44,312.68 1649.12,315.56 1649.04,315.55 1648.95,315.56 832.64,310.57 832.55,310.78 831.35,312.35 829.78,313.55 827.96,314.31 826,314.56 731.56,314.56 731.56,3614.87 858.13,3741.44 1942.44,3741.44
+5V on Internal_Layer 2 (split plane): 3916.91,20.1 3433.56,20.1 3433.56,1173 3433.31,1174.96 3432.55,1176.78 3431.35,1178.35 3429.78,1179.55 3427.96,1180.31 3426,1180.56 2844,1180.56 2842.04,1180.31 2840.22,1179.55 2838.65,1178.35 2837.45,1176.78 2836.69,1174.96 2836.44,1173 2836.44,940 2836.69,938.04 2837.14,936.97 2837.45,936.22 2838.65,934.65 2850.65,922.65 2852.22,921.45 2852.97,921.14 2854.04,920.69 2856,920.44 3062.44,920.44 3062.44,410.56 2329.56,410.56 2329.56,1059.93 2330.55,1061.22 2331.31,1063.04 2331.56,1065 2331.56,1383.44 2577,1383.44 2578.96,1383.69 2580.78,1384.45 2582.35,1385.65 2583.55,1387.22 2584.31,1389.04 2584.56,1391 2584.31,1392.91 2584.55,1393.22 2585.31,1395.04 2585.56,1397 2585.56,1550.44 2826.44,1550.44 2826.44,1470 2826.5,1469.5 2826.44,1469 2826.69,1467.04 2827.45,1465.22 2828.65,1463.65 2830.22,1462.45 2832.04,1461.69 2834,1461.44 3646,1461.44 3680,1461.44 3681.96,1461.69 3683.78,1462.45 3685.35,1463.65 3686.55,1465.22 3687.31,1467.04 3687.56,1469 3687.56,1763 3687.56,2884 3687.31,2885.96 3686.55,2887.78 3685.35,2889.35 3683.78,2890.55 3681.96,2891.31 3680,2891.56 3041.56,2891.56 3041.56,3567 3041.31,3568.96 3040.55,3570.78 3039.35,3572.35 3037.78,3573.55 3035.96,3574.31 3034,3574.56 2239.56,3574.56 2237.16,3574.56 2237.16,3916.91 3916.91,3916.91
DVDD on Internal_Layer 2 (split plane): 3026.44,2884 3026.69,2882.04 3027.45,2880.22 3028.65,2878.65 3030.22,2877.45 3032.04,2876.69 3034,2876.44 3672.44,2876.44 3672.44,1763 3672.44,1476.56 3646,1476.56 2841.56,1476.56 2841.56,1558 2841.31,1559.96 2840.55,1561.78 2839.35,1563.35 2837.78,1564.55 2835.96,1565.31 2834,1565.56 2491.56,1565.56 2491.56,1847 2491.56,2252 2491.31,2253.96 2490.55,2255.78 2489.35,2257.35 2487.78,2258.55 2485.96,2259.31 2484,2259.56 2316.56,2259.56 2316.56,2428.44 2505,2428.44 2506.96,2428.69 2508.78,2429.45 2510.35,2430.65 2511.55,2432.22 2512.31,2434.04 2512.56,2436 2512.56,2595.25 2513.31,2597.04 2513.56,2599 2513.56,2732 2513.31,2733.96 2512.55,2735.78 2511.35,2737.35 2509.78,2738.55 2507.96,2739.31 2506,2739.56 2437.56,2739.56 2437.56,2907 2437.31,2908.96 2436.55,2910.78 2435.35,2912.35 2433.78,2913.55 2433.56,2913.64 2433.56,3264 2433.31,3265.96 2432.55,3267.78 2431.35,3269.35 2429.78,3270.55 2427.96,3271.31 2426,3271.56 2245.12,3271.56 2245.12,3559.44 3026.44,3559.44

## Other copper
internal_Layer 1 (plane layer: these items are gaps in the copper):
  lines w15: -44,66 66,-44 ; 3839,1449 3840,1448
Internal_Layer 2 (plane layer: these items are gaps in the copper):
  lines w15: 826,307 724,307 724,3618 855,3749 1950,3749 1950,3264 2426,3264 2426,2907 ; 831,303 1649,308 1842,305 1842,817 ; 1841,806 1841,899 1576,899 1560,915 1560,1044 1560,1636 1915,1636 2029,1636 2029,1973 1972,1973 1972,2206 2038.56,2206 2038.56,2364.56 2007,2396.12 2007,2641.56 2007,2807 2430,2807 ; 1946.13,2199.66 1952.47,2206 ; 1988,3933 2215,3933 2229.6,3918.4 2229.6,3567 2361,3567 2822,3567 3034,3567 3034,2884 3680,2884 3680,1763 3680,1469 3646,1469 2834,1469 ; 2010,3931 3936,3931 3936,3847 3936,1368 3936,64 3936,0 3935,-1 3360,-1 ; 2011,3931 -5,3931 -5,1 3111,1 ; 2237.56,3260.48 2237.56,3565.48 ; 2237.56,3566 2238.56,3566 2239.56,3567 ; 2322,1072 2322,403 3070,403 3070,928 2856,928 2844,940 2844,1173 3426,1173 3426,0 3115,0 ; 2324,1065 2324,1391 2577,1391 ; 2430,2907 2430,2732 2506,2732 2506,2599 ; 2505,2599 2505,2436 2309,2436 2309,2252 2484,2252 2484,1847 2484,1558 2685,1558 ; 2578,1397 2578,1551 ; 2678,1558 2834,1558 2834,1470

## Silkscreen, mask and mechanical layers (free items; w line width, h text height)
Top Overlay:
  drawing of 588 lines, arcs and shapes, not listed
  text "2" at 1154.98,3822 h30
  text "1" at 1052,3821 h30
  text "3" at 1271,3821.33 h30
  text "+5V" at 3484,3589 h40 r90
  text "GND" at 3032,3577.49 h40 r90
  text "2" at 1156.98,3523 h30
  text "1" at 1054,3522 h30
  text "3" at 1273,3522.33 h30
  text "2" at 1154.98,3476 h30
  text "1" at 1052,3475 h30
  text "3" at 1271,3475.33 h30
  text "+5V_EXT" at 3516,3466 h30
  text "3" at 2293,3450 h40
  text "1" at 2453,3450 h40
  text "2" at 2374,3449 h40
  text "3" at 3661,3393 h40
  text "LHE7909-X / Demoboard / 2023-04" at 175,3363 h60
  text "DVDD=3.3V" at 2471,3304.33 h30
  text "DVDD=1.8V" at 2146,3303 h30
  text "2" at 3658,3283 h40
  text "CLKSEL=1" at 1990,3202.31 h30
  text "2" at 1154.98,3186 h30
  text "1" at 1052,3185 h30
  text "3" at 1271,3185.33 h30
  text "1" at 2261,3177 h40
  text "1" at 3658,3176.65 h40
  text "IN8_N" at 644,3145.32 h30
  text "2" at 1152.98,3143 h30
  text "1" at 1050,3142 h30
  text "3" at 1269,3142.33 h30
  text "+5V_Ctrl" at 3525,3104 h30
  text "2" at 2260,3093 h40
  text "IN8_P" at 646,3042.32 h30
  text "3" at 2261,2996 h40
  text "CLKSEL=0" at 1993,2985.31 h30
  text "45" at 3757.5,2958.48 h40
  text "46" at 3849,2958.48 h40
  text "IN7_N" at 642,2944.32 h30
  text "2" at 1152.98,2850 h30
  text "1" at 1050,2849 h30
  text "3" at 1269,2849.33 h30
  text "IN7_P" at 644,2841.32 h30
  text "2" at 1152.98,2810 h30
  text "1" at 1050,2809 h30
  text "3" at 1269,2809.33 h30
  text "IN6_N" at 638,2744.32 h30
  text "BIASINV" at 2048.69,2742 h30 r90
  text "BIAS_SHD" at 1940.68,2740 h30 r90
  text "IN6_P" at 644,2639.32 h30
  text "DRDY#" at 3343,2617.33 h30
  text "IN5_N" at 642,2547.32 h30
  text "BIASIN" at 2047.69,2526 h30 r90
  text "2" at 1147.98,2522 h30
  text "1" at 1045,2521 h30
  text "3" at 1264,2521.33 h30
  text "GPIO4" at 3350,2519.31 h30
  text "BIAS_ELEC" at 1689.68,2490 h30 r90
  text "2" at 1152.98,2475 h30
  text "1" at 1050,2474 h30
  text "3" at 1269,2474.33 h30
  text "IN5_P" at 644,2440.32 h30
  text "GPIO3" at 3351,2416.33 h30
  text "IN4_N" at 644,2349.32 h30
  text "GPIO2" at 3355,2322 h30
  text "IN4_P" at 642,2244.32 h30
  text "DOUT" at 3351,2219.31 h30
  text "2" at 1156.98,2188 h30
  text "1" at 1054,2187 h30
  text "3" at 1273,2187.33 h30
  text "2" at 1156.98,2153 h30
  text "1" at 1054,2152 h30
  text "3" at 1273,2152.33 h30
  text "IN3_N" at 640,2146.32 h30
  text "GPIO1" at 3351,2115.31 h30
  text "IN3_P" at 642,2046.32 h30
  text "DAISY_IN" at 3328,2021.32 h30
  text "IN2_N" at 640,1941.32 h30
  text "SCLK" at 3362,1921.31 h30
  text "2" at 1149.98,1870 h30
  text "1" at 1047,1869 h30
  text "3" at 1266,1869.33 h30
  text "IN2_P" at 638,1841.32 h30
  text "2" at 1145.98,1820 h30
  text "1" at 1043,1819 h30
  text "3" at 1262,1819.33 h30
  text "DVDD" at 3365,1807 h30
  text "IN1_N" at 638,1737.32 h30
  text "CS#" at 3376,1720.33 h30
  text "IN1_P" at 646,1634.32 h30
  text "START" at 3349,1629.31 h30
  text "2" at 1152.98,1531 h30
  text "1" at 1050,1530 h30
  text "3" at 1269,1530.33 h30
  text "DVDD" at 3349,1519 h30
  text "2" at 1151.34,1487.36 h30
  text "3" at 1267.36,1486.69 h30
  text "1" at 1048.36,1486.36 h30
  text "RESET#" at 3333,1416.33 h30
  text "PWDN#" at 3333,1300.33 h30
  text "DIN" at 3372,1216 h30
  text "2" at 1160.98,1204 h30
  text "1" at 1058,1203 h30
  text "3" at 1277,1203.33 h30
  text "BIAS_ELEC" at 615,1165 h30
  text "BIAS_ELEC" at 233,1156 h30
  text "DGND" at 3360,1100.31 h30
  text "+" at 1880,1093 h30
  text "AGND" at 2836,1065.31 h30
  text "-2.5V" at 3070,1065.31 h30
  text "REF_ELEC" at 505,943 h30
  text "2" at 2432.98,929 h30
  text "+" at 2640,704 h30
  text "+" at 2551,702 h30
  text "1" at 959,691 h40
  text "3" at 746,690 h40
  text "2" at 857,689 h40
  text "+" at 2016,651 h30
  text "1" at 3770,543 h40
  text "2" at 3870,543 h40
Mechanical 1:
  the board outline again, w10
